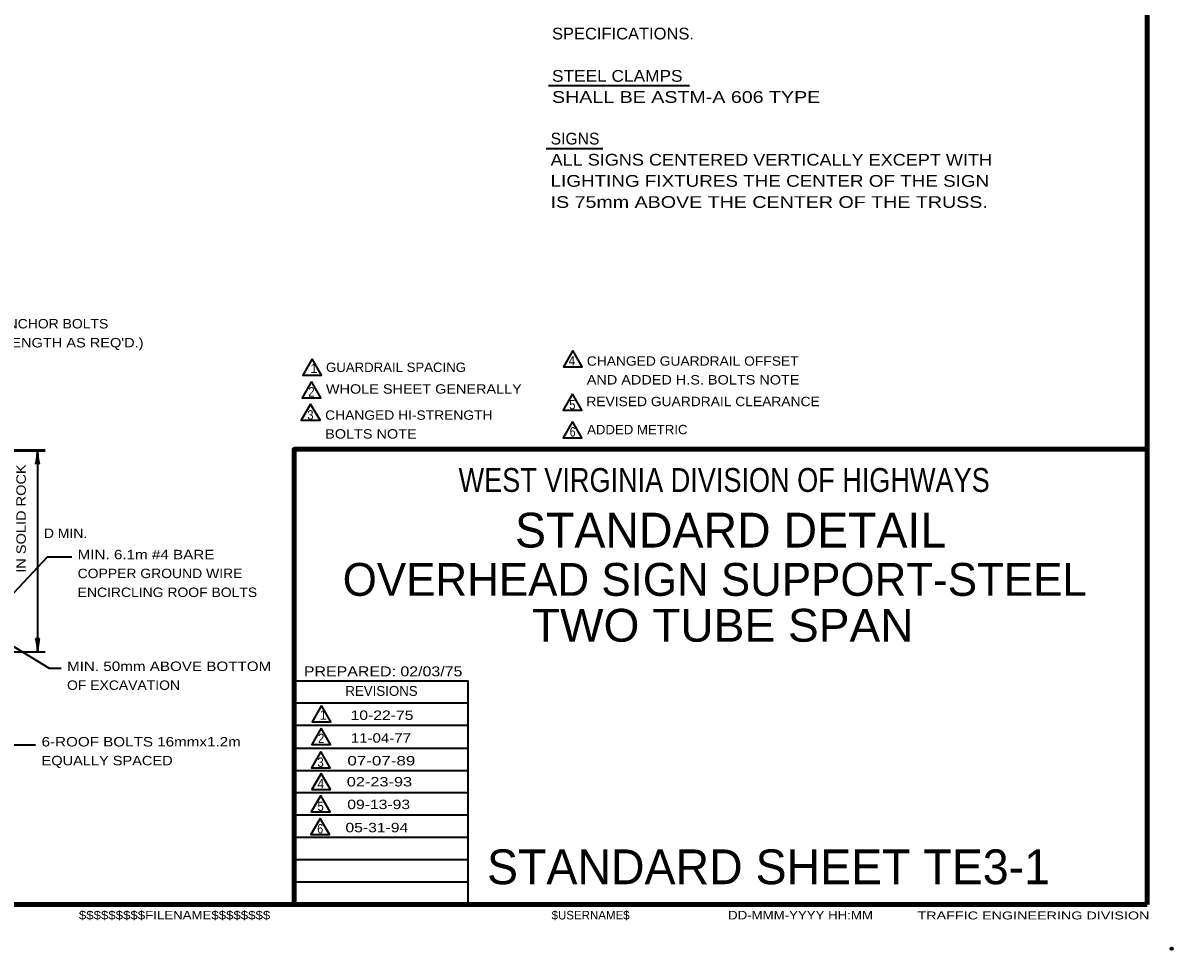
# Model space of a CAD drawing. Extents: x -34 to 822, y -23 to 521.
# Drawn here: x 527.6 to 821.5, y -23 to 213.8 of the extents above; entities that cross this region are included whole.
import ezdxf
from ezdxf.enums import TextEntityAlignment as Align

# ---------------------------------------------------------------- set-up
doc = ezdxf.new("R2010")
doc.units = 0
doc.header["$LTSCALE"] = 1.2
doc.header["$PDMODE"] = 32
doc.header["$PDSIZE"] = 0.6
doc.layers.add('1', color=7, linetype='Continuous', lineweight=35)
doc.layers.add('61', color=7, linetype='Continuous', lineweight=35)

msp = doc.modelspace()

# ---------------------------------------------------------------- linework, layer by layer
at = {"layer": '1', "lineweight": 158}
for q in [(814.9, 514.74), (814.9, 104.94), (23.3, -11.36)]:
    msp.add_line((814.9, -11.36), q, dxfattribs=at)
at = {"layer": '1', "lineweight": 13}
msp.add_line((814.9, -11.36), (814.9, 514.74), dxfattribs=at)
at = {"layer": '1'}
for p, q in [((661.905, 197.852), (697.935, 197.852)), ((661.325, 181.758), (675.771, 181.758)), ((531.336, 104.639), (531.336, 53.207)), ((519.888, 53.207), (533.28, 53.207)), ((641.4, 40.04), (596.9, 40.04)), ((641.4, 34.34), (596.9, 34.34)), ((641.4, 28.54), (596.9, 28.54)), ((641.4, 22.84), (596.9, 22.84)), ((641.4, 17.14), (596.9, 17.14)), ((641.4, 11.44), (596.9, 11.44)), ((641.4, 5.74), (596.9, 5.74)), ((641.4, 0.04), (596.9, 0.04)), ((641.4, -5.66), (596.9, -5.66))]:
    msp.add_line(p, q, dxfattribs=at)
at = {"layer": '1', "lineweight": 53}
msp.add_line((517.992, 104.639), (533.28, 104.639), dxfattribs=at)
at = {"layer": '1'}
for points in [[(668.141, 130.143), (665.741, 125.986), (670.541, 125.986)], [(601.538, 127.988), (599.138, 123.831), (603.938, 123.831)], [(601.36, 122.249), (598.96, 118.092), (603.76, 118.092)], [(668.029, 119.053), (665.629, 114.896), (670.429, 114.896)], [(601.127, 116.488), (598.727, 112.331), (603.527, 112.331)], [(668.067, 112.036), (665.667, 107.88), (670.466, 107.88)], [(603.895, 39.508), (601.495, 35.351), (606.295, 35.351)], [(603.831, 33.721), (601.431, 29.565), (606.231, 29.565)], [(603.718, 27.733), (601.318, 23.576), (606.118, 23.576)], [(603.836, 22.159), (601.436, 18.002), (606.236, 18.002)], [(603.692, 16.496), (601.293, 12.34), (606.092, 12.34)], [(603.555, 10.661), (601.155, 6.504), (605.955, 6.504)]]:
    msp.add_lwpolyline(points, close=True, dxfattribs=at)
at = {"layer": '1', "lineweight": 158}
msp.add_lwpolyline([(596.9, -11.36), (596.9, 104.94), (814.9, 104.94)], dxfattribs=at)
at = {"layer": '1'}
for points in [[(514.176, 56.519), (533.904, 77.423), (540.072, 77.423)], [(524.688, 54.911), (534.336, 49.055), (537.36, 49.055)], [(512.52, 45.071), (524.04, 29.471), (530.784, 29.471)], [(641.4, -11.36), (641.4, 45.74), (596.9, 45.74)]]:
    msp.add_lwpolyline(points, dxfattribs=at)
at = {"layer": '1', "lineweight": 40}
for centre, major_axis, ratio, start_param, end_param in [((531.086, 103.292), (0.212, 2.125), 0.07063, 3.1407148, 5.41811), ((531.676, 103.327), (-0.189, 2.16), 0.122415, 0.8963533, 3.1415927), ((531.008, 54.521), (0.189, -2.16), 0.122415, 0.8963533, 3.1415927), ((531.008, 54.521), (0.189, -2.16), 0.122415, 0.8963533, 3.1415927), ((531.598, 54.557), (-0.212, -2.125), 0.07063, 3.1407148, 5.41811), ((531.598, 54.557), (-0.212, -2.125), 0.07063, 3.1407148, 5.41811)]:
    msp.add_ellipse(centre, major_axis=major_axis, ratio=ratio, start_param=start_param, end_param=end_param, dxfattribs=at)
at = {"layer": '1'}
msp.add_point((821.2, -22.66), dxfattribs=at)
at = {"layer": '61', "lineweight": 53}
for q in [(662.2, -11.36), (662.2, -11.36), (662.2, -11.36), (662.5, -11.36), (662.5, -11.36)]:
    msp.add_line((814.9, -11.36), q, dxfattribs=at)

# ---------------------------------------------------------------- texts
at = {"layer": '1'}
for s, height, width, p in [('SPECIFICATIONS.', 3, 1.05, (662.806, 209.602)), ('STEEL CLAMPS', 3, 1.1, (662.806, 198.802)), ('SHALL BE ASTM-A 606 TYPE', 3, 1.25, (662.806, 193.402)), ('ALL SIGNS CENTERED VERTICALLY EXCEPT WITH', 3, 1.15, (662.45, 177.375)), ('LIGHTING FIXTURES THE CENTER OF THE SIGN', 3, 1.2, (662.45, 171.975)), ('IS 75mm ABOVE THE CENTER OF THE TRUSS.', 3, 1.25, (662.45, 166.575)), ('ANCHOR BOLTS', 2.419, 1.1, (521.328, 135.791)), ("(LENGTH AS REQ'D.)", 2.419, 1.15, (521.328, 130.943)), ('GUARDRAIL SPACING', 2.4, 1.05, (605.056, 124.67)), ('4', 2.4, 0.95, (667.068, 126.377)), ('CHANGED GUARDRAIL OFFSET', 2.4, 1.1, (671.694, 126.272)), ('AND ADDED H.S. BOLTS NOTE', 2.4, 1.15, (671.694, 121.472)), ('2', 2.4, 0.9, (600.537, 118.4)), ('WHOLE SHEET GENERALLY', 2.4, 1.15, (605.038, 119.136)), ('REVISED GUARDRAIL CLEARANCE', 2.4, 1.1, (671.582, 115.939)), ('3', 2.4, 0.9, (600.261, 112.515)), ('CHANGED HI-STRENGTH', 2.4, 1.1, (604.839, 112.458)), ('5', 2.4, 0.9, (667.204, 115.121)), ('BOLTS NOTE', 2.4, 1.15, (604.839, 107.658)), ('6', 2.4, 0.85, (667.321, 108.184)), ('ADDED METRIC', 2.4, 1.05, (671.778, 108.764)), ('D MIN.', 2.419, 1.1, (532.968, 82.271)), ('MIN. 6.1m #4 BARE', 2.419, 1.2, (541.584, 76.828)), ('COPPER GROUND WIRE', 2.419, 1.1, (541.584, 72.009)), ('ENCIRCLING ROOF BOLTS', 2.419, 1.1, (541.584, 67.19)), ('MIN. 50mm ABOVE BOTTOM', 2.419, 1.2, (538.872, 48.292)), ('PREPARED: 02/03/75', 2.537, 1.2, (599.4, 46.94)), ('OF EXCAVATION', 2.419, 1.1, (538.872, 43.473)), ('2', 2.4, 0.9, (603.01, 29.9)), ('6-ROOF BOLTS 16mmx1.2m', 2.419, 1.2, (532.368, 29.02)), ('EQUALLY SPACED', 2.419, 1.15, (532.368, 24.201)), ('3', 2.4, 0.9, (602.853, 23.801)), ('4', 2.4, 0.95, (602.867, 18.33)), ('5', 2.4, 0.9, (602.868, 12.565)), ('6', 2.4, 0.85, (602.81, 6.809)), ('$$$$$$$$$FILENAME$$$$$$$$', 2.2, 1.15, (541.9, -15.16)), ('DD-MMM-YYYY HH:MM', 2.2, 1.15, (707.8, -15.16)), ('TRAFFIC ENGINEERING DIVISION', 2.031, 1.35, (756.2, -15.16))]:
    msp.add_text(s, height=height, dxfattribs=dict(at, width=width)).set_placement(p)
for s, height, p in [('SIGNS', 3, (662.45, 182.775)), ('1', 2.4, (601.087, 124.384)), ('REVISIONS', 2.537, (610, 41.94)), ('1', 2.4, (603.48, 35.877)), ('STANDARD SHEET TE3-1 ', 8.881, (646.2, -6.16)), ('$USERNAME$', 2.2, (662.7, -15.16))]:
    msp.add_text(s, height=height, dxfattribs=at).set_placement(p)
at = {"layer": '1', "width": 1.15}
msp.add_text('IN SOLID ROCK', height=2.419, rotation=90, dxfattribs=at).set_placement((528.336, 87.239), align=Align.CENTER)
at = {"layer": '1'}
for s, height, width, p in [('WEST VIRGINIA DIVISION OF HIGHWAYS', 6.089, 0.85, (706.8, 94.04)), ('TWO TUBE SPAN', 8.391, 1.05, (706.424, 55.779)), ('10-22-75', 2.4, 1.25, (619.367, 35.805)), ('11-04-77', 2.4, 1.2, (619.077, 29.992)), ('07-07-89', 2.4, 1.35, (619.19, 24.179)), ('02-23-93', 2.4, 1.3, (618.704, 18.811)), ('09-13-93', 2.4, 1.25, (618.512, 13.024)), ('05-31-94', 2.4, 1.25, (618.046, 7.111))]:
    msp.add_text(s, height=height, dxfattribs=dict(at, width=width)).set_placement(p, align=Align.CENTER)
for s, height, p in [('STANDARD DETAIL', 8.881, (708.45, 79.84)), ('OVERHEAD SIGN SUPPORT-STEEL', 8.391, (704.404, 67.499))]:
    msp.add_text(s, height=height, dxfattribs=at).set_placement(p, align=Align.CENTER)

doc.saveas('drawing.dxf')
